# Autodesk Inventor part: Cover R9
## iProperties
Shininess: 64.0
Length Units: 11272
Angle Units: 11279
Time Units: 11290
Mass Units: 11286
Length Display Precision: 3
Angle Display Precision: 2
Compacted: True
Part Number: Cover R9
Document SubType Name: Modeling
Created: 2004-02
Designer: lebovipa
Manufacturer: Standard
Standards Organization: Custom
Density: 0.0
Volumn: 0.0
Area: 0.0
PropertySet Name: Model Information
Control State: 0
Master: False
Checked Out: False
Author: lebovipa
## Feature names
1. Revolution1
2. Split1
3. Mirror1
4. Shell4
5. Fillet3
6. Shell5
7. Hole1
8. Chamfer1
